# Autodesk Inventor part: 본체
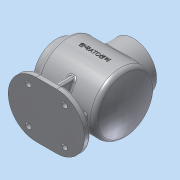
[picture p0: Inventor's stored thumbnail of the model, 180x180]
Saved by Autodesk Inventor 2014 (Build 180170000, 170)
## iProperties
Created: 2023-01
Part Number: 본체
Material: 알루미늄 6061
Document SubType Name: Modeling
Designer: dg
Mass: 1037.87 g
Surface Area: 1159.88 cm^2
Volume: 382.978 cm^3
Density: 2.71 g/cm^3
Appearance: 알루미늄 - 평지
Author: dg
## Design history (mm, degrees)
sketch "스케치1"
  geometry: L1 (0, 0)-(-122, 0); L2 (-122, 0)-(-122, 38); L3 (-122, 38)-(-110, 38); L4 (-110, 38)-(-110, 50); L5 (-110, 50)-(-10.913, 50); A1 r 120 centre (-120, 0) between (0, 0) and (-10.913, 50)
  constraints: 10 end point, 2 perpendicular, 2 point on circle, 1 centre point, 1 horizontal, 1 horizontal alignment, 1 parallel, 1 vertical
  dimensions: "d0" = 120 radius of A1; "d1" = 122 distance of L1.start L1.end; "d9" = 110 horizontal distance of L1.start L4.end; "d10" = 100 diameter of L5 L1; "d11" = 76 diameter of L3 L1
revolve "회전1" sketch "스케치1" stored, may be unused: angle "d3" = 90 deg
node "작업 평면2"
sketch "스케치4"
  geometry: L1 (-122, 38)-(-110, 38) reference; L2 (-122, -38)-(-122, 38) reference; L3 (-122, 0)-(0, 0); L4 (-110, 50)-(-10.913, 50) reference; L5 (-122, 0)-(-122, 27); L6 (-122, 27)-(-105, 27); L7 (-105, 27)-(-105, 45); L8 (-105, 45)-(-14.17, 45); A1 r 120 centre (-120, 0) between (-10.913, -50) and (-10.913, 50) reference; A2 r 115 centre (-120, 0) between (-5, 0) and (-14.17, 45); 2 further points
  constraints: 10 end point, 3 point on circle, 2 midpoint, 2 parallel, 2 perpendicular, 1 centre point, 1 coincident, 1 horizontal, 1 point on line
  dimensions: "d12" = 54 diameter of L6 L3; "d13" = 90 diameter of L8 L3; "d14" = 5 radial gap between concentric circles of A1 A2; "d15" = 17 distance of L5.end L6.end
revolve "회전2" sketch "스케치4" stored, may be unused: angle "d16" = 90 deg
fillet "모깎기1" dims "d19" = 8
fillet "모깎기2" dims "d20" = 3
node "작업 평면5"
node "작업 평면6"
sketch "스케치7"
  geometry: L1 (110, 42)-(110, -42) reference; C1 r 38 at (59, 0); 1 further point
  constraints: 1 centre point, 1 horizontal alignment
  dimensions: "d23" = 51 distance from line of C1.centre L1; "d24" = 76 diameter of C1
extrude "돌출2" join sketch "스케치7" stored distance "d25" = 12; taper "d26" = 0 deg
sketch "스케치8"
  geometry: C1 r 38 at (0, 0) reference; C2 r 27 at (0, 0); 1 further point
  constraints: 1 centre point, 1 coincident
  dimensions: "d27" = 54 diameter of C2
extrude "돌출3" cut sketch "스케치8" stored distance "d28" = 12; taper "d29" = 0 deg
sketch "스케치9" dims "d30" = 65
  geometry: C1 r 27 at (0, 0) reference; C2 r 38 at (0, 0) reference; 3 further points
  constraints: 2 horizontal alignment, 1 coincident, 2 other
hole "구멍1" sketch "스케치9" at (-32.5, 0) diameter "d31" = 3.242; stored, may be unused: countersink angle "d35" = 90 deg, drill point angle "d37" = 118 deg; dims "d32" = 8, "d33" = 4, "d34" = 2, "d36" = 10
chamfer "모따기1" distance "d41" = 1; stored, may be unused: second distance "d42" = 2, angle "d43" = 45 deg
node "작업 평면7"
sketch "스케치10"
  geometry: L1 (76, -46)-(42, -46); L2 (42, 46)-(76, 46); C1 r 38 at (59, 0) reference; A1 r 46 centre (42, 0) between (42, 46) and (42, -46); A2 r 46 centre (76, 0) between (76, -46) and (76, 46); 2 further points
  constraints: 4 end point, 4 point on circle, 4 tangent, 2 centre point, 2 horizontal, 1 horizontal alignment, 1 midpoint, 1 vertical alignment
  dimensions: "d45" = 92 distance between parallel lines of L2 L1; "d46" = 126 dimension on A1 A2
extrude "돌출4" join sketch "스케치10" distance "d47" = 10; taper "d48" = 0 deg
sketch "스케치11"
  geometry: L1 (-42, 46)-(-76, 46) reference; L2 (-54, 35)-(-64, 35); L3 (-64, 35)-(-64, -35); L4 (-64, -35)-(-54, -35); L5 (-54, -35)-(-54, 35); A1 r 46 centre (-76, 0) between (-76, 46) and (-76, -46) reference; 4 further points
  constraints: 8 end point, 3 midpoint, 2 parallel, 1 horizontal, 1 horizontal alignment, 1 perpendicular, 1 vertical alignment
  dimensions: "d50" = 70 distance of L2.end L3.end; "d51" = 10 distance of L2.start L2.end
extrude "돌출5" join sketch "스케치11" stored distance "d52" = 12; taper "d53" = 0 deg
fillet "모깎기3" dims "d54" = 3
node "작업 평면8"
sketch "스케치12"
  geometry: L1 (-29.641, 20)-(-35, 0); L2 (39.641, 20)-(45, 0); L3 (-38, 20)-(47.827, 20) reference; L4 (-55, 0)-(-12, 0) reference; L5 (22, 0)-(65, 0) reference; L6 (0, 0)-(0, 34.293) reference; L7 (10, 0)-(10, 34.293) reference; L8 (-12, 0)-(22, 0) reference; L9 (-58, -10)-(-58, -3) reference; 1 further point
  constraints: 4 end point, 4 point on line
  dimensions: "d57" = 105 deg angle of L4 L1; "d58" = 105 deg angle of L5 L2; "d59" = 80 distance of L2.end L1.end; "d60" = 23 distance from line of L1.end L9
feature "리브1" dims "d61" = 1, "d62" = 10, "d63" = 0, "d64" = 0, "d65" = 1, "d66" = 1
feature "리브2" dims "d67" = 1, "d68" = 10, "d69" = 0, "d70" = 0, "d71" = 1, "d72" = 1
fillet "모깎기4" dims "d73" = 3
fillet "모깎기5" dims "d74" = 3
sketch "스케치13" dims "d75" = 65
  geometry: C1 r 38 at (0, 0) reference; C2 r 27 at (0, 0) reference; 2 further points
  constraints: 2 horizontal alignment, 1 coincident, 2 other
hole "구멍2" sketch "스케치13" at (-32.5, 0) diameter "d76" = 3.242; stored, may be unused: countersink angle "d80" = 90 deg, drill point angle "d82" = 118 deg; dims "d77" = 8, "d78" = 4, "d79" = 2, "d81" = 10
sketch "스케치14"
  geometry: L1 (-57, 38)-(-61, 38) reference; C1 r 4.5 at (-89, 30); C2 r 4.5 at (-29, 30); C3 r 4.5 at (-89, -30); C4 r 4.5 at (-29, -30); A1 r 43 centre (-76, 0) between (-76, 43) and (-76, -43) reference; 2 further points
  constraints: 4 centre point, 3 equal radius, 2 horizontal alignment, 2 vertical alignment, 1 midpoint
  dimensions: "d86" = 60 distance of C2.centre C1.centre; "d87" = 60 distance of C3.centre C1.centre; "d88" = 30 vertical distance of A1.centre C1.centre; "d89" = 30 horizontal distance of point (-59, 38) C1.centre; "d90" = 9 diameter of C1
extrude "돌출6" cut sketch "스케치14" distance "d91" = 12; taper "d92" = 0 deg
node "작업 평면10"
  node "작업 평면9"
sketch "스케치15"
  geometry: L1 (-122, -38)-(-122, 38) reference; L2 (-42, -80)-(4, -80) reference; 2 further points
  constraints: 1 other
  dimensions: "d94" = 63 distance from line of L1 point (-59, 0); "d95" = 80 distance from line of L2 point (-59, 0)
feature "엠보싱1" sketch "스케치15" dims "d12" = 54, "d13" = 90, "d14" = 5, "d15" = 17, "d51" = 10, "d77" = 8, "d84" = 360 deg, "d96" = 0.5, "d97" = 0, "d101" = 45 deg
fillet "모깎기6" dims "d98" = 3
chamfer "모따기2" distance "d99" = 1; stored, may be unused: second distance "d100" = 2, angle "d101" = 45 deg
node "솔리드1"
pattern_circular "원형 패턴1" dims angle "d39" = 360 deg
pattern_circular "원형 패턴2" dims angle "d84" = 360 deg
node "투영된 루프1"
other parameters: "d22" = 64, "d93" = 104.75
